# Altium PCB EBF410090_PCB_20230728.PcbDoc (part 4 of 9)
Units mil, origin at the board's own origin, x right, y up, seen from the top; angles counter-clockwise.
Board outline 5393.69 x 3858.26 mil, 6 copper layers (TOP, GND02, ART03, ART04, PWR05, BOTTOM), stack 47.2 mil thick; 570 components, 437 nets, 2015 pads, 1260 vias.
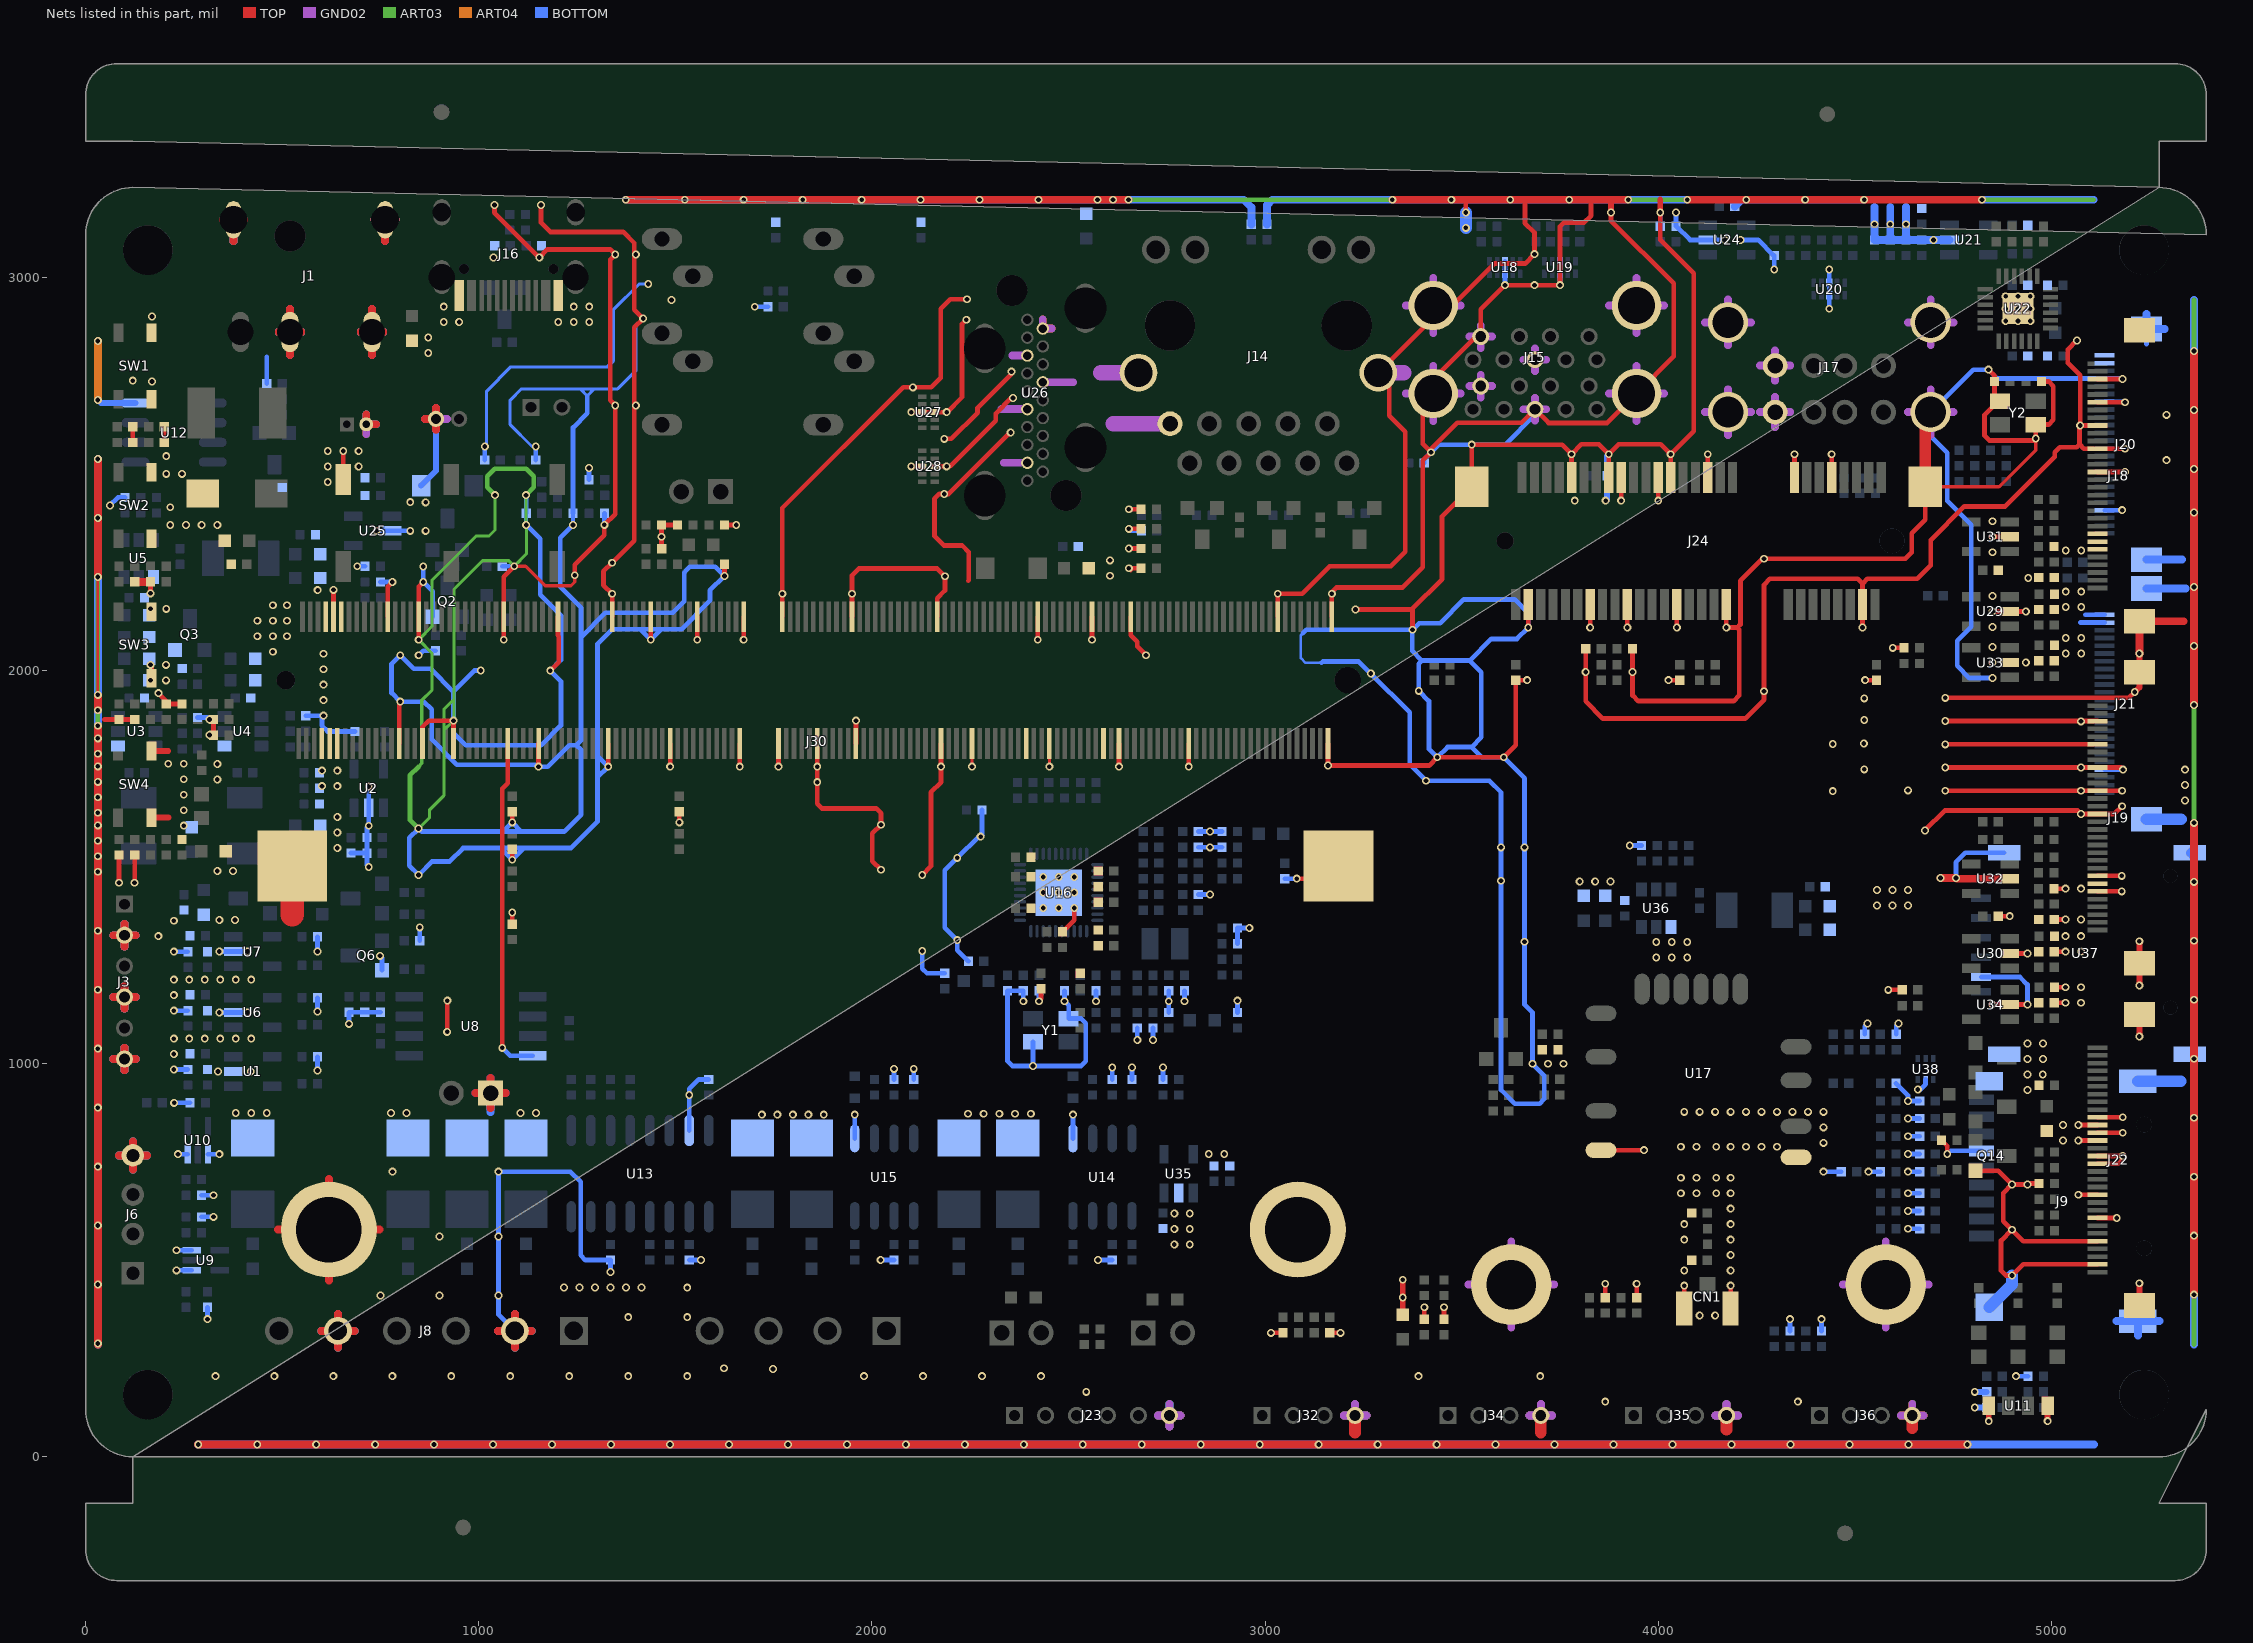
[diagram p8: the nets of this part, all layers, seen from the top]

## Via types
v1: diameter 20, hole 12, TOP to BOTTOM, 1260 vias

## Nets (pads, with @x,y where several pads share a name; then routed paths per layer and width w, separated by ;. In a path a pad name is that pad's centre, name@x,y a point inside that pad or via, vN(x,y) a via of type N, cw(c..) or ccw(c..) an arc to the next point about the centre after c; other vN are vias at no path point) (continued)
GND: C1.2 C2.2 C3.2 C4.2 C5.2 C6.2 C9.2 C10.2 C11.2 C12.2 C13.2 C14.2 C15.2 C16.2 C17.2 C18.1 C21.2 C22.2 C23.2 C24.2 C25.2 C26.2 C27.1 C30.2 C31.2 C32.2 C33.2 C34.2 C35.2 C36.2 C37.1 C39.2 C40.2 C41.2 C42.2 C43.2 C47.2 C48.2 C49.2 C50.2 C51.2 C52.2 C53.2 C54.2 C55.2 C56.2 C57.2 C58.2 C59.2 C60.2 C61.2 C62.2 C63.2 C64.2 C65.2 C66.2 C67.2 C68.2 C69.2 C70.2 C73.2 C74.2 C75.2 C76.2 C79.2 C80.2 C81.2 C82.2 C83.2 C84.2 C85.2 C86.2 C87.2 C88.2 C89.2 C90.2 C91.2 C92.2 C93.2 C94.2 C95.2 C96.2 C97.2 C98.2 C99.2 C100.2 C101.2 C102.2 C103.2 C104.2 C105.2 C107.2 C108.2 C110.2 C111.2 C112.2 C113.2 C116.2 C117.2 C118.2 C119.2 C120.1 C121.2 C122.2 C123.2 C124.2 C125.2 C126.2 C127.2 C128.2 C129.2 C130.2 C131.2 C136.2 C137.2 C138.2 C139.2 C140.2 C141.2 C142.2 C143.2 C144.2 C145.2 C150.2 C151.2 C152.2 C153.2 C154.2 C155.2 C162.2 C163.2 C164.2 C166.2 C167.2 C170.2 C171.2 C172.2 C173.2 C174.2 C175.2 C176.2 C177.2 C178.2 C181.2 C182.2 C183.2 C184.2 C185.2 C186.2 C187.2 C191.2 C192.2 C431.2 CN1.2 CN1.3 D1.1 D2.2 D7.1 D8.1 D9.1 D10.1 D11.1 D12.1 D13.1 D14.1 D15.1 D16.1 D17.1 D18.1 D21.1 D22.1 D23.1 D24.1 D28.1 D29.1 D30.1 D31.1 D32.1 D33.1 D34.1 D35.1 D36.1 D47.1 D48.1 D49.1 D50.1 D51.1 D52.1 D53.1 D54.1 J1.1 J1.2 J1.3 J1.5 J2.2 J3.2 J3.4 J3.6 J5.1 J6.4 J7.2 J8.2 J8.5 J9.6 J9.10 J9.11 J9.12 J9.13 J14.10 J14.15 J14.16 J15.4 J15.7 J15.13 J15.16 J15.19 J15.20 J15.21 J15.22 J16.A1 J16.A12 J16.B1 J16.B12 J17.4 J17.5 J17.6 J17.10 J17.11 J17.12 J18.6 J18.7 J18.8 J18.16 J18.19 J18.22 J18.25 J18.28 J18.31 J18.32 J19.6 J19.7 J19.8 J19.16 J19.19 J19.22 J19.25 J19.28 J19.31 J19.32 J20.4 J20.18 J20.21 J20.23 J20.24 J20.25 J20.26 J21.4 J21.23 J21.24 J21.25 J21.26 J22.2 J22.5 J22.8 J22.11 J22.15 J22.16 J22.18 J22.19 J22.20 J22.21 J22.31 J22.32 J23.6 J24.4 J24.9 J24.15 J24.18 J24.21 J24.26 J24.27 J24.29 J24.34 J24.35 J24.37 J24.40 J24.43 J24.50 J24.53 J24.54 J30.1 J30.2 J30.15 J30.38 J30.53 J30.56 J30.60 J30.63 J30.74 J30.77 J30.80 J30.94 J30.102 J30.103 J30.124 J30.125 J30.134 J30.143 J30.144 J30.145 J30.146 J30.157 J30.164 J30.169 J30.179 J30.180 J30.193 J30.198 J30.206 J30.207 J30.220 J30.228 J30.229 J30.234 J30.237 J30.249 J30.250 J30.251 J30.252 J30.253 J30.254 J30.261 J30.262 J32.4 J34.4 J35.4 J36.4 L8.2 L9.2 Q2.2 Q3.2 Q6.2 Q14.2 R2.2 R5.2 R6.2 R8.2 R13.2 R15.2 R18.2 R21.2 R22.2 R25.2 R30.2 R32.2 R34.2 R36.2 R75.2 R76.2 R77.2 R78.2 R98.2 R103.2 R104.2 R105.2 R111.2 R114.2 R115.2 R116.2 R121.1 R144.2 R148.2 R151.2 R153.2 R155.2 R173.2 R174.2 R175.2 R176.2 R182.2 R188.2 R192.1 R195.2 R199.2 R205.2 R219.2 R220.2 R221.2 SS1.1 SS2.1 SS5.1 SS6.1 SW1.1 SW1.2 SW2.1 SW2.2 SW3.1 SW3.2 SW4.1 SW4.2 U1.2 U2.2 U3.1 U4.1 U5.1 U6.2 U7.2 U8.4 U9.1 U9.3 U10.1 U10.3 U11.1 U11.4 U12.4 U13.15 U14.5 U15.5 U16.41 U17.1 U17.5 U18.3 U18.8 U19.3 U19.8 U20.3 U20.8 U21.2 U22.25 U24.2 U25.2 U26.2 U26.5 U26.8 U26.11 U26.17 U27.3 U27.8 U28.3 U28.8 U29.2 U30.2 U31.2 U32.2 U33.2 U34.2 U35.2 U36.1 U37.5 U37.8 U37.9 U37.10 U37.11 U38.2 Y1.2 Y1.4 Y2.2 Y2.4 Z1.1 Z2.2 Z3.2 Z4.1 Z5.1 Z7.1 Z8.1 Z9.1 Z10.1 Z11.1 Z13.1 Z23.1 | length 106230.6
  TOP w6.8: v1(31,1937.88) v1(31,2237.88)
  TOP w8: v1(1090,2265) 1119,2265 1168.59,2215.41 1234.41,2215.41 1244,2225 v1(1244,2242) ; v1(2254.41,1755.23) J30.94@2254.41,1813.7 ; v1(2451.26,1755.23) J30.74@2451.26,1813.7 ; J24.54@4679.19,2467.26 4679.45,2467 4867,2467 4960,2560 v1(4960,2590)
  TOP w12: 47.18,1875.32 Z5.1@85,1875.32 C63.2@125,1875.32 ; v1(85,1460) Z23.1@85,1530.32 ; C60.2@119.68,2580 Z1.1@119.68,2620 ; v1(124.37,1460) 125,1460.63 C192.2@125,1530.32 ; v1(165,2014.14) 167.63,2011.51 SW3.2@167.63,1980.06 ; v1(165,2196) C37.1@165,2225.32 ; v1(185,1942.15) 205,1922.15 C18.1@205,1914.68 R8.2@245,1914.68 ; Z4.1@199.68,2580 C61.2@199.68,2620 ; C27.1@325.32,1835 R15.2@325.32,1875 ; J30.251@630.39,2136.54 v1(630.39,2205) ; C1.2@655,2485.24 v1(655,2558) ; J30.237@768.19,2136.54 768.19,2213.19 v1(780,2225) ; J30.234@797.71,1813.7 797.71,1918.3 v1(800,1920.59) ; v1(846.93,2078.07) J30.229@846.93,2136.54 846.93,2213.19 v1(858.74,2225) ; J30.228@856.76,1813.7 856.76,1856.27 872.66,1872.17 v1(935.5,1872.17) J30.220@935.5,1813.7 ; v1(919.4,1080.63) 920,1081.23 v1(920,1160) ; v1(1039.63,3184) 1039.63,3164.38 v1(1153.94,3050.07) 1174.63,3070.76 1334.12,3070.76 v1(1346.88,3058) 1334,3045.12 1334,2686.88 v1(1346.88,2674) 1346.88,2397.83 v1(1319.37,2370.32) 1319.37,2344.38 1244,2269.01 v1(1244,2242) ; v1(1059.51,1040) 1059.51,1699.51 1073.3,1713.3 J30.206@1073.3,1813.7 ; v1(1063.46,2078.07) J30.207@1063.46,2136.54 1063.46,2238.46 v1(1090,2265) ; C53.2@1085,1354.68 v1(1085,1384.15) ; v1(1085,1518.52) R36.2@1085,1545.32 ; v1(1085,1613.52) C56.2@1085,1640.32 ; v1(1152.04,1755.23) J30.198@1152.04,1813.7 ; v1(1158.37,3184) 1158.37,3138.63 1181.77,3115.23 1367.29,3115.23 1395.35,3087.17 1395.35,3062 v1(1399.35,3058) 1395.35,3054 1395.35,2917.65 v1(1418,2895) 1395.35,2872.35 1395.35,2678 v1(1399.35,2674) 1395.35,2670 1395.35,2330.05 v1(1339.05,2273.75) 1317.05,2251.75 1317.05,2217.01 v1(1339.05,2195.01) J30.179@1339.05,2136.54 ; v1(1181.57,1999.33) 1203.57,2021.33 1203.57,2087.19 1201.26,2089.5 J30.193@1201.26,2136.54 ; v1(1329.2,1755.23) J30.180@1329.2,1813.7 ; v1(1437.48,2078.07) J30.169@1437.48,2136.54 ; C185.2@1465,2309.68 1464.68,2310 v1(1464.68,2340) C186.2@1464.68,2370 Z7.1@1505.32,2370 ; v1(1486.68,1755.23) J30.164@1486.68,1813.7 ; v1(1510,1613.52) R151.2@1510,1640.32 ; v1(1555.58,2078.07) J30.157@1555.59,2136.54 ; v1(1624.68,2240) R220.2@1624.68,2270 ; Z10.1@1624.68,2370 v1(1654.68,2370) ; v1(1663.85,1755.23) J30.146@1663.85,1813.7 ; v1(1673.69,2078.07) J30.145@1673.7,2136.54 ; v1(1762.28,1755.23) J30.144@1762.28,1813.7 ; J30.143@1772.12,2136.54 v1(1772.12,2195.01) 1772.12,2413.12 2079.51,2720.51 2103.49,2720.51 v1(2104,2720) 2151,2720 2175,2744 2175,2920 2199,2944 v1(2242,2944) ; J30.134@1860.71,1813.7 v1(1860.71,1755.23) v1(1860.71,1715.86) 1860.71,1661 1872.71,1649 2011,1649 2023,1637 v1(2023,1607.6) 2001,1585.6 2001,1514.84 v1(2023,1492.84) ; J30.125@1949.29,2136.54 v1(1949.29,2195.01) 1949.29,2242 1966.29,2259 2165.89,2259 v1(2185.51,2239.38) 2185.51,2203.26 2165.82,2183.57 J30.103@2165.82,2136.54 ; J30.124@1959.13,1813.7 v1(1959.13,1872.17) ; v1(2100,2519) U28.8@2128.25,2519 ; v1(2100,2657) U27.8@2128.25,2657 U27.3@2159.75,2657 v1(2190,2657) 2191.07,2657 2229,2694.93 2229,2881 v1(2240,2892) ; v1(2128,1479.6) 2150,1501.6 2150,1690 2175.67,1715.67 v1(2175.67,1755.23) J30.102@2175.67,1813.7 ; U28.3@2159.75,2519 v1(2190,2519) 2199,2519 2315,2635 2315,2653.42 2354.58,2693 v1(2359,2693) ; v1(2184,2589) 2201.99,2589 2268.68,2655.69 2268.68,2668.33 2355,2754.65 v1(2355,2760) ; 2245,2228 2246,2229 2246,2301 2229,2318 2183,2318 2159,2342 2159,2437 2171,2449 v1(2184,2449) 2195,2449 2351.35,2605.35 v1(2352.65,2605.35) ; v1(2421.72,2078.07) J30.77@2421.73,2136.54 ; v1(2425,1158.52) 2425,1160 2430,1165 C100.2@2430,1190.32 ; R115.2@2484.68,1335 2514.37,1364.69 v1(2514.37,1395.63) ; v1(2559.51,2078.07) J30.63@2559.52,2136.54 ; v1(2628.42,1755.23) J30.56@2628.42,1813.7 ; v1(2653.36,2310) D30.1@2684.5,2310 ; v1(2653.36,2360) D28.1@2684.5,2360 ; v1(2653.36,2410) D29.1@2684.5,2410 ; J30.53@2657.95,2136.54 2657.95,2089.49 2675,2072.44 2675,2061 v1(2697.3,2038.7) ; v1@2657.95,2255.41 v1(2653.36,2260) D31.1@2684.5,2260 ; v1(2805.59,1755.23) J30.38@2805.59,1813.7 ; v1(3015,315) D50.1@3045.32,315 ; J30.15@3031.96,2136.54 v1(3031.98,2195.01) ; v1(3031.98,2195.01) 3094,2195.01 3163.99,2265 3320,2265 3356.65,2301.65 3356.65,2607.35 3315.65,2648.35 3315.65,2729.64 J14.15@3287.85,2757.44 3427.62,2897.21 J15.19@3427.62,2927.91 3475.91,2927.91 3583,3035 3661.26,3035 v1(3685,3058.74) 3685,3114 3661,3138 3661,3196.34 3660,3197.34 ; v1(3080.32,1470.32) 3154.13,1470.32 J30.261@3186.49,1502.68 ; J30.2@3159.92,1813.7 v1(3159.92,1757.92) 3416.92,1757.92 v1(3438,1779) v1(3607,1779) 3637.85,1809.85 C184.2@3637.85,1975.32 v1(3666.57,1975.32) ; D49.1@3164.68,315 v1(3191.48,315) ; J30.1@3169.76,2136.54 v1(3169.78,2195.01) ; v1(3169.78,2195.01) 3169.78,2199 3181.78,2211 3350.01,2211 3401.12,2262.11 3401.12,2534 v1(3422.12,2555) ; v1(3230,2155) 3372.99,2155 ; v1(3375,2103.52) 3375,2152.99 3372.99,2155 ; D48.1@3405,349.68 v1(3405,380) ; D47.1@3455,349.68 v1(3455,380) ; 3509,3197.34 3510.63,3195.71 v1(3510.63,3165) ; v1(3669.35,2108.92) J24.50@3669.35,2168.04 ; J24.43@3779.59,2490.88 v1(3779.59,2550) ; D36.1@3815.32,2055 v1(3815.32,1995.88) 3815.32,1921.68 3859.35,1877.65 4221,1877.65 4269,1925.65 v1(4269,1947) 4269,2218 4284,2233 4507.74,2233 4519.74,2221 ; v1(3826.83,2108.92) J24.40@3826.83,2168.04 ; 3828,3197.34 3829,3196.34 3829,3157 3811,3139 3760,3139 3750,3129 v1(3750,2980) v1(3685,2980) v1(3610,2980) 3548.49,2918.49 J15.4@3548.49,2849.17 3536.17,2849.17 3427.62,2740.62 J15.20@3427.62,2704.29 3401.12,2677.79 3401.12,2576 v1(3422.12,2555) ; U17.5@3854.39,779.83 v1(3964,779.83) ; D52.1@3865,404.68 v1(3865,440) ; J24.37@3874.07,2490.88 v1(3874.07,2550) ; v1(3879.53,3164.61) 3879.53,3143.95 4039.24,2984.24 4039.24,2798.58 J15.21@3944.95,2704.29 3870.01,2629.35 3721.06,2629.35 J15.16@3686.28,2664.13 3652.15,2630 3488.62,2630 3422.12,2563.5 v1(3422.12,2555) ; v1(3905.57,2431.76) J24.35@3905.57,2490.88 ; v1(3921.32,2108.92) J24.34@3921.32,2168.04 ; D35.1@3934.68,2055 v1(3934.68,1995.88) 3934.68,1936.44 3949,1922.12 4191.65,1922.12 4206,1936.47 4206,2104.01 4201.09,2108.92 ; D51.1@3945,404.68 v1(3945,440) ; v1(4000.06,2431.76) J24.29@4000.06,2490.88 ; v1(4005,3165) 4005,3095 4090,3010 4090,2608.45 v1(4031.55,2550) ; v1(4026.28,1975.32) C181.2@4055,1975.32 ; J24.27@4031.55,2490.88 v1(4031.55,2550) ; v1(4047.3,2108.92) J24.26@4047.3,2168.04 ; CN1.3@4065.94,376.8 v1(4065.94,435.11) ; J24.21@4126.04,2490.88 v1(4126.04,2550) ; J24.18@4173.29,2168.04 v1(4173.29,2108.92) 4201.09,2108.92 ; CN1.2@4184.06,376.8 v1(4184.06,435.11) ; J24.15@4346.51,2490.88 v1(4346.51,2550) ; J24.9@4441,2490.88 v1(4441,2550) ; v1(4519.74,2108.92) J24.4@4519.74,2168.04 4519.74,2221 ; v1(4526.28,1975.32) C183.2@4555,1975.32 ; v1(4585,1187.4) C153.2@4620.32,1187.4 ; v1(4596.6,2057.4) C150.2@4625.32,2057.4 ; v1(4678.26,1593) 4728.76,1643.5 5066.35,1643.5 v1(5075,1634.85) J19.16@5117.47,1634.85 5160.32,1634.85 v1(5180,1654.53) ; J24.54@4679.19,2467.26 4679.19,2383.19 4644.65,2348.65 4644.65,2300 4628.65,2284 4613.44,2284 4613.4,2283.96 4575.7,2283.96 4575.66,2284 v1(4269,2284) 4264.61,2284 4209,2228.39 4209,2116.83 4201.09,2108.92 ; R199.2@4720.32,805 4735,790.32 v1(4735,770) ; v1(4730,1693.9) v1(5075,1693.9) J19.19@5117.47,1693.9 v1(5180,1693.9) ; v1(4730,1752.96) v1(5075,1752.96) J19.22@5117.47,1752.96 5177.04,1752.96 v1(5182.32,1747.68) ; v1(4730,1812.01) J19.25@5117.47,1812.01 ; v1(4730,1871.07) 5074.37,1871.07 v1(5075,1870.44) 5075.63,1871.07 J19.28@5117.47,1871.07 ; v1(4730,1930.13) 5197.13,1930.13 v1(5212,1945) ; Q14.2@4806.5,727.5 4864.76,727.5 v1(4899.64,692.62) ; v1(4840,2765) 4855.32,2749.68 C119.2@4855.32,2735 4855.32,2698.93 Y2.4@4869.72,2684.53 4864.52,2684.53 4830,2650.01 4830,2597 4842,2585 4955,2585 v1(4960,2590) 4960.28,2590.28 Y2.2@4960.28,2625.47 4993,2625.47 5005,2637.47 5005,2723 4993,2735 C120.1@4974.68,2735 ; v1(4849.41,1150) U34.2@4894.21,1150 v1(4939.01,1150) ; v1(4850,2150) U29.2@4894.21,2150 v1(4935,2150) ; v1(4850,2340) U31.2@4894.21,2340 ; C136.2@4864.68,1375 v1(4894,1375) ; U30.2@4894.21,1280 v1(4939.01,1280) ; R192.1@4968.32,695 4941.39,695 v1(4939.01,692.62) v1(4899.64,692.62) ; R176.2@5006.68,1445 v1(5035.68,1445) ; C155.2@5007,1154.68 v1(5036,1154.68) ; C138.2@5007,1284.68 v1(5036,1284.68) ; C145.2@5007,1366.32 v1(5036,1366.32) ; R188.2@5007.68,1194 v1(5036,1194.05) v1(5036,1194.05) ; v1(5065,2839.37) 5041.71,2816.08 5041.71,2782.12 5073.04,2750.79 v1(5073.04,2622.96) ; v1(5068.63,666.42) J22.11@5117.47,666.42 ; v1(5068.63,804.22) J22.18@5117.47,804.22 ; v1(5068.63,843.59) J22.20@5117.47,843.59 ; J22.2@5117.47,489.26 4928.1,489.26 v1(4900,461.16) 4884,461.16 4872,473.16 4872,549.73 v1(4899.64,577.37) ; J22.5@5117.47,548.31 4928.7,548.31 v1(4899.64,577.37) ; J22.8@5117.47,607.37 v1(5166.31,607.37) ; J22.15@5117.47,745.16 5169.46,745.16 5181.46,757.16 v1(5181.46,764.85) J22.16@5117.47,764.85 ; J22.19@5117.47,823.9 v1(5181.46,823.9) ; J22.21@5117.47,863.27 v1(5181.46,863.27) ; J19.6@5117.47,1438 v1(5179,1438) ; J19.8@5117.47,1477.37 v1(5179,1477.37) ; J18.16@5117.47,2504.85 v1(5187,2504.85) ; J18.22@5117.47,2622.96 v1(5073.04,2622.96) ; J18.25@5117.47,2682.01 v1(5187,2682.01) ; J18.28@5117.47,2741.07 v1(5181,2741.07) ; v1(5187,2563.9) J18.19@5117.47,2563.9 5082.69,2563.9 5071.59,2575 ; 3372.99,2155 3450.12,2232.13 3450.12,2391.73 J24.53@3525.65,2467.26 v1(3525.65,2574.35) 3755.24,2574.35 v1(3779.59,2550) ; v1(3779.59,2550) 3804.59,2575 3849.07,2575 v1(3874.07,2550) ; v1(3874.07,2550) 3899.07,2575 4006.55,2575 v1(4031.55,2550) ; 4519.74,2221 4531.74,2233 4659,2233 4693,2267 4693,2331.6 4778.4,2417 4882.7,2417 5008.63,2542.93 5008.63,2554.59 5021.51,2567.47 5064.06,2567.47 5071.59,2575 ; v1(4899.64,577.37) 4877.64,599.37 4877.64,670.62 v1(4899.64,692.62) ; 5071.59,2575 5071.59,2621.51 v1(5073.04,2622.96)
  TOP w15: SW4.2@167.01,1625.64 210.64,1625.64 ; SW4.1@167.01,1794.94 210.06,1794.94 ; C431.2@3350,361.5 v1(3350,405) v1(3350,450) ; v1(3879.53,3164.61) 3880,3165.08 3880,3197.34 ; v1(4005,3165) 4005,3197.34 ; v1(4840.52,90.52) U11.1@4840.52,129.26 ; v1(4990.52,90.52) U11.4@4990.52,129.26 ; v1(5212,1945) 5223.77,1956.77 J19.31@5223.77,1995.08 v1(5223.77,2042.95) ; J22.32@5223.77,384.92 v1(5223.77,441.23) ; v1(5223.77,1068.77) J22.31@5223.77,1125.08 ; v1(5223.77,1198.61) J19.32@5223.77,1254.92 v1(5223.77,1311.23)
  TOP w20: v1@31,285 v1(31,287.88) v1(31,437.88) v1(31,587.88) v1(31,737.88) v1(31,887.88) v1(31,1037.88) v1(31,1187.88) v1(31,1337.88) v1(31,1487.88) v1(31,1527.25) v1(31,1566.62) v1(31,1605.99) v1(31,1637.88) v1(31,1677.25) v1(31,1716.62) v1(31,1755.99) v1(31,1787.88) v1(31,1827.25) v1(31,1859.14) ; v1(31,1898.51) v1(31,1937.88) ; v1(31,2237.88) v1(31,2387.88) v1(31,2537.88) ; 70.06,1011.58 J3.6@98.74,1011.58 ; 70.06,1169.06 J3.4@98.74,1169.06 ; 70.06,1326.54 J3.2@98.74,1326.54 ; 84.43,766.54 J6.4@120,766.54 ; 98.74,982.9 J3.6@98.74,1011.58 ; 98.74,1040.26 J3.6@98.74,1011.58 ; 98.74,1140.38 J3.4@98.74,1169.06 ; 98.74,1197.74 J3.4@98.74,1169.06 ; 98.74,1297.86 J3.2@98.74,1326.54 ; 98.74,1355.22 J3.2@98.74,1326.54 ; 120,730.97 J6.4@120,766.54 ; 120,802.11 J6.4@120,766.54 ; R25.2@125,2225.32 C37.1@165,2225.32 ; 127.42,1011.58 J3.6@98.74,1011.58 ; 127.42,1169.06 J3.4@98.74,1169.06 ; 127.42,1326.54 J3.2@98.74,1326.54 ; 155.57,766.54 J6.4@120,766.54 ; v1@285,31 v1(286.25,31) v1(436.25,31) v1(586.25,31) v1(736.25,31) v1(886.25,31) v1(1036.25,31) v1(1186.25,31) v1(1336.25,31) v1(1486.25,31) v1(1636.25,31) v1(1786.25,31) v1(1936.25,31) v1(2086.25,31) v1(2236.25,31) v1(2386.25,31) v1(2536.25,31) v1(2686.25,31) v1(2836.25,31) v1(2986.25,31) v1(3136.25,31) v1(3286.25,31) v1(3436.25,31) v1(3586.25,31) v1(3736.25,31) v1(3886.25,31) v1(4036.25,31) v1(4186.25,31) v1(4336.25,31) v1(4486.25,31) v1(4636.25,31) v1(4786.25,31) ; 349.28,3146.28 J1.1@376,3146.28 ; 376,3092.01 J1.1@376,3146.28 ; 402.72,3146.28 J1.1@376,3146.28 ; 489.51,577.48 SS6.1@618.58,577.48 ; 491.03,2860.78 J1.2@519.7,2860.78 ; 519.7,2802.56 J1.2@519.7,2860.78 ; 519.7,2919 J1.2@519.7,2860.78 ; 548.37,2860.78 J1.2@519.7,2860.78 ; 599.2,320.17 J8.5@641.66,320.17 ; 618.58,448.41 SS6.1@618.58,577.48 ; 618.58,706.55 SS6.1@618.58,577.48 ; 641.66,277.71 J8.5@641.66,320.17 ; 641.66,362.63 J8.5@641.66,320.17 ; 684.12,320.17 J8.5@641.66,320.17 ; 699.63,2860.78 J1.3@728.3,2860.78 ; 713.59,2650.72 J7.2@713.59,2625.98 738.33,2625.98 ; 728.3,2802.56 J1.3@728.3,2860.78 ; 728.3,2919 J1.3@728.3,2860.78 ; 735.08,3146.28 J1.5@761.8,3146.28 ; 747.65,577.48 SS6.1@618.58,577.48 ; 756.97,2860.78 J1.3@728.3,2860.78 ; 761.8,3092.01 J1.5@761.8,3146.28 ; 788.52,3146.28 J1.5@761.8,3146.28 ; 863.3,2639.93 J2.2@890.99,2639.93 ; 890.99,2612.24 J2.2@890.99,2639.93 ; 890.99,2667.62 J2.2@890.99,2639.93 ; 991.48,925 J5.1@1030,925 ; 1030,886.48 J5.1@1030,925 ; 1030,963.52 J5.1@1030,925 ; 1049.2,320.17 J8.2@1091.66,320.17 ; 1068.52,925 J5.1@1030,925 ; 1091.66,277.71 J8.2@1091.66,320.17 ; 1091.66,362.63 J8.2@1091.66,320.17 ; 1134.12,320.17 J8.2@1091.66,320.17 ; v1(1373.69,3197.34) v1(1523.69,3197.34) v1(1673.69,3197.34) v1(1823.69,3197.34) v1(1973.69,3197.34) v1(2123.69,3197.34) v1(2273.69,3197.34) v1(2423.69,3197.34) v1(2573.69,3197.34) v1(2613.06,3197.34) v1(2652.43,3197.34) ; v1(3323.69,3197.34) v1(3473.69,3197.34) 3509,3197.34 v1(3623.69,3197.34) 3660,3197.34 v1(3773.69,3197.34) 3828,3197.34 3880,3197.34 v1(3923.69,3197.34) ; v1(4073.69,3197.34) v1(4223.69,3197.34) v1(4373.69,3197.34) v1(4523.69,3197.34) v1(4823.69,3197.34) ; v1(4717.82,1471.97) v1(4757.19,1471.97) 4759.16,1470 U32.2@4894.21,1470 ; v1(5223.77,2042.95) J18.32@5223.77,2124.92 5335.92,2124.92 ; v1(5362.69,412.23) v1(5362.69,562.23) v1(5362.69,712.23) v1(5362.69,862.23) v1(5362.69,1012.23) v1(5362.69,1162.23) v1(5362.69,1312.23) v1(5362.69,1462.23) v1(5362.69,1612.23) ; v1(5362.69,1912.23) v1(5362.69,2062.23) v1(5362.69,2212.23) v1(5362.69,2401.6) v1(5362.69,2512.23) v1(5362.69,2662.23) v1(5362.69,2812.23)
  TOP w30: 3228.86,61.14 J32.4@3228.86,105.01 ; 3701.3,61.3 J34.4@3701.3,105.01 ; 4173.74,68.74 J35.4@4173.74,105.01 ; 4646.18,72.18 J36.4@4646.18,105.01 ; J24.54@4679.19,2467.26 4679.19,2643.26 J17.6@4692.97,2657.04
  TOP w60: 525.07,1378.07 J30.262@525.07,1502.68
  GND02 w20: 70.06,1011.58 J3.6@98.74,1011.58 ; 70.06,1169.06 J3.4@98.74,1169.06 ; 70.06,1326.54 J3.2@98.74,1326.54 ; 84.43,766.54 J6.4@120,766.54 ; 98.74,982.9 J3.6@98.74,1011.58 ; 98.74,1040.26 J3.6@98.74,1011.58 ; 98.74,1140.38 J3.4@98.74,1169.06 ; 98.74,1197.74 J3.4@98.74,1169.06 ; 98.74,1297.86 J3.2@98.74,1326.54 ; 98.74,1355.22 J3.2@98.74,1326.54 ; 120,730.97 J6.4@120,766.54 ; 120,802.11 J6.4@120,766.54 ; 127.42,1011.58 J3.6@98.74,1011.58 ; 127.42,1169.06 J3.4@98.74,1169.06 ; 127.42,1326.54 J3.2@98.74,1326.54 ; 155.57,766.54 J6.4@120,766.54 ; 349.28,3146.28 J1.1@376,3146.28 ; 376,3092.01 J1.1@376,3146.28 ; 402.72,3146.28 J1.1@376,3146.28 ; 491.03,2860.78 J1.2@519.7,2860.78 ; 509.2,577.48 SS6.1@618.58,577.48 ; 519.7,2802.56 J1.2@519.7,2860.78 ; 519.7,2919 J1.2@519.7,2860.78 ; 548.37,2860.78 J1.2@519.7,2860.78 ; 599.2,320.17 J8.5@641.66,320.17 ; 618.58,468.1 SS6.1@618.58,577.48 ; 618.58,686.86 SS6.1@618.58,577.48 ; 641.66,277.71 J8.5@641.66,320.17 ; 641.66,362.63 J8.5@641.66,320.17 ; 684.12,320.17 J8.5@641.66,320.17 ; 699.63,2860.78 J1.3@728.3,2860.78 ; 713.59,2601.24 J7.2@713.59,2625.98 ; 713.59,2650.72 J7.2@713.59,2625.98 ; 727.96,577.48 SS6.1@618.58,577.48 ; 728.3,2802.56 J1.3@728.3,2860.78 ; 728.3,2919 J1.3@728.3,2860.78 ; 735.08,3146.28 J1.5@761.8,3146.28 ; 738.33,2625.98 J7.2@713.59,2625.98 ; 756.97,2860.78 J1.3@728.3,2860.78 ; 761.8,3092.01 J1.5@761.8,3146.28 ; 788.52,3146.28 J1.5@761.8,3146.28 ; 863.3,2639.93 J2.2@890.99,2639.93 ; 890.99,2612.24 J2.2@890.99,2639.93 ; 890.99,2667.62 J2.2@890.99,2639.93 ; 918.68,2639.93 J2.2@890.99,2639.93 ; 991.48,925 J5.1@1030,925 ; 1030,886.48 J5.1@1030,925 ; 1030,963.52 J5.1@1030,925 ; 1049.2,320.17 J8.2@1091.66,320.17 ; 1068.52,925 J5.1@1030,925 ; 1091.66,277.71 J8.2@1091.66,320.17 ; 1091.66,362.63 J8.2@1091.66,320.17 ; 1134.12,320.17 J8.2@1091.66,320.17 ; 2329.51,2664.49 U26.11@2395.17,2664.49 ; 2335.92,2528.08 U26.17@2395.17,2528.08 ; 2356.91,2800.91 U26.5@2395.17,2800.91 ; U26.8@2434.54,2732.92 2512.08,2732.92 ; 2434.54,2892.23 U26.2@2434.54,2869.46 2457.31,2869.46 ; 2727.74,105.01 J23.6@2756.42,105.01 ; 2756.42,76.33 J23.6@2756.42,105.01 ; 2756.42,133.69 J23.6@2756.42,105.01 ; 2785.1,105.01 J23.6@2756.42,105.01 ; 2973.76,577.48 SS5.1@3083.14,577.48 ; 3083.14,468.1 SS5.1@3083.14,577.48 ; 3083.14,686.86 SS5.1@3083.14,577.48 ; 3192.52,577.48 SS5.1@3083.14,577.48 ; 3200.18,105.01 J32.4@3228.86,105.01 ; 3228.86,76.33 J32.4@3228.86,105.01 ; 3228.86,133.69 J32.4@3228.86,105.01 ; 3257.54,105.01 J32.4@3228.86,105.01 ; 3357.61,2704.29 J15.20@3427.62,2704.29 ; 3357.61,2927.91 J15.19@3427.62,2927.91 ; 3427.62,2634.28 J15.20@3427.62,2704.29 ; 3427.62,2774.3 J15.20@3427.62,2704.29 ; 3427.62,2857.9 J15.19@3427.62,2927.91 ; 3427.62,2997.92 J15.19@3427.62,2927.91 ; 3497.63,2704.29 J15.20@3427.62,2704.29 ; 3497.63,2927.91 J15.19@3427.62,2927.91 ; 3516.65,437.78 SS2.1@3626.03,437.78 ; 3519.81,2723.19 J15.13@3548.49,2723.19 ; 3519.81,2849.17 J15.4@3548.49,2849.17 ; 3548.49,2694.51 J15.13@3548.49,2723.19 ; 3548.49,2751.87 J15.13@3548.49,2723.19 ; 3548.49,2820.49 J15.4@3548.49,2849.17 ; 3548.49,2877.85 J15.4@3548.49,2849.17 ; 3577.17,2723.19 J15.13@3548.49,2723.19 ; 3577.17,2849.17 J15.4@3548.49,2849.17 ; 3626.03,328.4 SS2.1@3626.03,437.78 ; 3626.03,547.16 SS2.1@3626.03,437.78 ; 3657.6,2664.13 J15.16@3686.28,2664.13 ; 3657.6,2790.12 J15.7@3686.28,2790.12 ; 3672.62,105.01 J34.4@3701.3,105.01 ; 3686.28,2635.45 J15.16@3686.28,2664.13 ; 3686.28,2692.81 J15.16@3686.28,2664.13 ; 3686.28,2761.44 J15.7@3686.28,2790.12 ; 3686.28,2818.8 J15.7@3686.28,2790.12 ; 3701.3,76.33 J34.4@3701.3,105.01 ; 3701.3,133.69 J34.4@3701.3,105.01 ; 3714.96,2664.13 J15.16@3686.28,2664.13 ; 3714.96,2790.12 J15.7@3686.28,2790.12 ; 3729.98,105.01 J34.4@3701.3,105.01 ; 3735.41,437.78 SS2.1@3626.03,437.78 ; 3874.94,2704.29 J15.21@3944.95,2704.29 ; 3874.94,2927.91 J15.22@3944.95,2927.91 ; 3944.95,2634.28 J15.21@3944.95,2704.29 ; 3944.95,2774.3 J15.21@3944.95,2704.29 ; 3944.95,2857.9 J15.22@3944.95,2927.91 ; 3944.95,2997.92 J15.22@3944.95,2927.91 ; 4014.96,2704.29 J15.21@3944.95,2704.29 ; 4014.96,2927.91 J15.22@3944.95,2927.91 ; 4119.03,2657.04 J17.5@4177.23,2657.04 ; 4119.03,2885.39 J17.11@4177.23,2885.39 ; 4145.06,105.01 J35.4@4173.74,105.01 ; 4173.74,76.33 J35.4@4173.74,105.01 ; 4173.74,133.69 J35.4@4173.74,105.01 ; 4177.23,2598.84 J17.5@4177.23,2657.04 ; 4177.23,2715.24 J17.5@4177.23,2657.04 ; 4177.23,2827.19 J17.11@4177.23,2885.39 ; 4177.23,2943.59 J17.11@4177.23,2885.39 ; 4202.42,105.01 J35.4@4173.74,105.01 ; 4235.43,2657.04 J17.5@4177.23,2657.04 ; 4235.43,2885.39 J17.11@4177.23,2885.39 ; 4258.78,2657.04 J17.4@4297.3,2657.04 ; 4258.78,2775.15 J17.10@4297.3,2775.15 ; 4297.3,2618.52 J17.4@4297.3,2657.04 ; 4297.3,2695.56 J17.4@4297.3,2657.04 ; 4297.3,2736.63 J17.10@4297.3,2775.15 ; 4297.3,2813.67 J17.10@4297.3,2775.15 ; 4335.82,2657.04 J17.4@4297.3,2657.04 ; 4335.82,2775.15 J17.10@4297.3,2775.15 ; 4469.41,437.78 SS1.1@4578.79,437.78 ; 4578.79,328.4 SS1.1@4578.79,437.78 ; 4578.79,547.16 SS1.1@4578.79,437.78 ; 4617.5,105.01 J36.4@4646.18,105.01 ; 4634.77,2657.04 J17.6@4692.97,2657.04 ; 4634.77,2885.39 J17.12@4692.97,2885.39 ; 4646.18,76.33 J36.4@4646.18,105.01 ; 4646.18,133.69 J36.4@4646.18,105.01 ; 4674.86,105.01 J36.4@4646.18,105.01 ; 4688.17,437.78 SS1.1@4578.79,437.78 ; 4692.97,2598.84 J17.6@4692.97,2657.04 ; 4692.97,2715.24 J17.6@4692.97,2657.04 ; 4692.97,2827.19 J17.12@4692.97,2885.39 ; 4692.97,2943.59 J17.12@4692.97,2885.39 ; 4751.17,2657.04 J17.6@4692.97,2657.04 ; 4751.17,2885.39 J17.12@4692.97,2885.39
  GND02 w40: 2582.56,2757.44 J14.16@2678.01,2757.44 ; 2614.52,2627.52 J14.10@2758.13,2627.52 ; J14.15@3287.85,2757.44 3352.44,2757.44
  ART03 w8: v1(846.76,1597.75) 875,1625.99 875,1645.56 911,1681.56 911,1847.67 ; 846.76,1755.23 855,1763.47 855,1923.8 881,1949.8 881,2044 v1(846.93,2078.07) 881,2112.14 881,2229.8 993.2,2342 1026,2342 1041.26,2357.26 v1(1041.26,2445.87) ; v1(1120,2445.87) 1120,2370.32 v1(1120.32,2370) 1121.37,2368.95 1121.37,2296.37 v1(1090,2265) 1076,2279 1009.4,2279 937,2206.6 937,1926.6 ; 911,1847.67 v1(935.5,1872.17) 937,1873.67 937,1926.6 ; 911,1847.67 911,1900.6 937,1926.6
  ART03 w12: v1@31,285 v1(31,287.88) v1(31,437.88) v1(31,587.88) ; v1(31,737.88) v1(31,887.88) v1(31,1037.88) v1(31,1187.88) v1(31,1337.88) v1(31,1487.88) v1(31,1527.25) v1(31,1566.62) v1(31,1605.99) v1(31,1637.88) v1(31,1677.25) v1(31,1716.62) v1(31,1755.99) v1(31,1787.88) v1(31,1827.25) v1(31,1859.14) v1(31,1898.51) v1(31,1937.88) v1(31,2237.88) v1(31,2387.88) v1(31,2537.88) ; v1@285,31 v1(286.25,31) v1(436.25,31) v1(586.25,31) v1(736.25,31) v1(886.25,31) v1(1036.25,31) v1(1186.25,31) v1(1336.25,31) v1(1486.25,31) v1(1636.25,31) v1(1786.25,31) v1(1936.25,31) v1(2086.25,31) v1(2236.25,31) v1(2386.25,31) v1(2536.25,31) v1(2686.25,31) v1(2836.25,31) v1(2986.25,31) v1(3136.25,31) v1(3286.25,31) v1(3436.25,31) v1(3586.25,31) v1(3736.25,31) v1(3886.25,31) v1(4036.25,31) v1(4186.25,31) v1(4336.25,31) v1(4486.25,31) v1(4636.25,31) v1(4786.25,31) ; v1(846.76,1597.75) 824.76,1619.75 824.76,1733.23 846.76,1755.23 ; v1(1041.26,2445.87) 1021.26,2465.87 1021.26,2493.53 1040.73,2513 1120.53,2513 1140,2493.53 1140,2465.87 v1(1120,2445.87) ; v1(1523.69,3197.34) v1(1673.69,3197.34) ; v1(2123.69,3197.34) v1(2273.69,3197.34) v1(2423.69,3197.34) v1(2573.69,3197.34) v1(2613.06,3197.34) v1(2652.43,3197.34) v1(3323.69,3197.34) v1(3473.69,3197.34) v1(3623.69,3197.34) v1(3773.69,3197.34) v1(3923.69,3197.34) v1(4073.69,3197.34) v1(4223.69,3197.34) v1(4373.69,3197.34) v1(4523.69,3197.34) v1(4823.69,3197.34) 5107.51,3197.34 ; 5362.69,284.99 v1(5362.69,412.23) v1(5362.69,562.23) v1(5362.69,712.23) v1(5362.69,862.23) v1(5362.69,1012.23) v1(5362.69,1162.23) v1(5362.69,1312.23) v1(5362.69,1462.23) v1(5362.69,1612.23) v1(5362.69,1912.23) v1(5362.69,2062.23) v1(5362.69,2212.23) v1(5362.69,2401.6) v1(5362.69,2512.23) v1(5362.69,2662.23) v1(5362.69,2812.23) 5362.69,2942.16
  ART03 w20: v1(31,587.88) v1(31,737.88) ; 349.28,3146.28 J1.1@376,3146.28 ; 376,3092.01 J1.1@376,3146.28 ; 402.72,3146.28 J1.1@376,3146.28 ; 491.03,2860.78 J1.2@519.7,2860.78 ; 509.2,577.48 SS6.1@618.58,577.48 ; 519.7,2919 J1.2@519.7,2860.78 ; 548.37,2860.78 J1.2@519.7,2860.78 ; 599.2,320.17 J8.5@641.66,320.17 ; 618.58,468.1 SS6.1@618.58,577.48 ; 618.58,686.86 SS6.1@618.58,577.48 ; 641.66,277.71 J8.5@641.66,320.17 ; 641.66,362.63 J8.5@641.66,320.17 ; 684.12,320.17 J8.5@641.66,320.17 ; 699.63,2860.78 J1.3@728.3,2860.78 ; 727.96,577.48 SS6.1@618.58,577.48 ; 728.3,2919 J1.3@728.3,2860.78 ; 735.08,3146.28 J1.5@761.8,3146.28 ; 756.97,2860.78 J1.3@728.3,2860.78 ; 761.8,3092.01 J1.5@761.8,3146.28 ; 788.52,3146.28 J1.5@761.8,3146.28 ; 1049.2,320.17 J8.2@1091.66,320.17 ; 1091.66,277.71 J8.2@1091.66,320.17 ; 1091.66,362.63 J8.2@1091.66,320.17 ; 1134.12,320.17 J8.2@1091.66,320.17 ; 2727.74,105.01 J23.6@2756.42,105.01 ; 2756.42,76.33 J23.6@2756.42,105.01 ; 2756.42,133.69 J23.6@2756.42,105.01 ; 2785.1,105.01 J23.6@2756.42,105.01 ; 3200.18,105.01 J32.4@3228.86,105.01 ; 3228.86,76.33 J32.4@3228.86,105.01 ; 3228.86,133.69 J32.4@3228.86,105.01 ; 3257.54,105.01 J32.4@3228.86,105.01 ; 3672.62,105.01 J34.4@3701.3,105.01 ; 3701.3,76.33 J34.4@3701.3,105.01 ; 3701.3,133.69 J34.4@3701.3,105.01 ; 3729.98,105.01 J34.4@3701.3,105.01 ; 4145.06,105.01 J35.4@4173.74,105.01 ; 4173.74,76.33 J35.4@4173.74,105.01 ; 4173.74,133.69 J35.4@4173.74,105.01 ; 4202.42,105.01 J35.4@4173.74,105.01 ; 4617.5,105.01 J36.4@4646.18,105.01 ; 4646.18,76.33 J36.4@4646.18,105.01 ; 4646.18,133.69 J36.4@4646.18,105.01 ; 4674.86,105.01 J36.4@4646.18,105.01
  ART04 w20: v1(31,2687.88) v1(31,2837.88) ; 70.06,1011.58 J3.6@98.74,1011.58 ; 70.06,1169.06 J3.4@98.74,1169.06 ; 70.06,1326.54 J3.2@98.74,1326.54 ; 84.43,766.54 J6.4@120,766.54 ; 98.74,982.9 J3.6@98.74,1011.58 ; 98.74,1040.26 J3.6@98.74,1011.58 ; 98.74,1140.38 J3.4@98.74,1169.06 ; 98.74,1197.74 J3.4@98.74,1169.06 ; 98.74,1297.86 J3.2@98.74,1326.54 ; 98.74,1355.22 J3.2@98.74,1326.54 ; 120,730.97 J6.4@120,766.54 ; 120,802.11 J6.4@120,766.54 ; 127.42,1011.58 J3.6@98.74,1011.58 ; 127.42,1169.06 J3.4@98.74,1169.06 ; 127.42,1326.54 J3.2@98.74,1326.54 ; 155.57,766.54 J6.4@120,766.54 ; 349.28,3146.28 J1.1@376,3146.28 ; 376,3092.01 J1.1@376,3146.28 ; 402.72,3146.28 J1.1@376,3146.28 ; 491.03,2860.78 J1.2@519.7,2860.78 ; 509.2,577.48 SS6.1@618.58,577.48 618.58,468.1 ; 519.7,2802.56 J1.2@519.7,2860.78 ; 519.7,2919 J1.2@519.7,2860.78 ; 548.37,2860.78 J1.2@519.7,2860.78 ; 599.2,320.17 J8.5@641.66,320.17 ; 641.66,277.71 J8.5@641.66,320.17 ; 641.66,362.63 J8.5@641.66,320.17 ; 684.12,320.17 J8.5@641.66,320.17 ; 699.63,2860.78 J1.3@728.3,2860.78 ; 713.59,2601.24 J7.2@713.59,2625.98 ; 713.59,2650.72 J7.2@713.59,2625.98 ; 728.3,2802.56 J1.3@728.3,2860.78 ; 728.3,2919 J1.3@728.3,2860.78 ; 735.08,3146.28 J1.5@761.8,3146.28 ; 738.33,2625.98 J7.2@713.59,2625.98 ; 756.97,2860.78 J1.3@728.3,2860.78 ; 761.8,3092.01 J1.5@761.8,3146.28 ; 788.52,3146.28 J1.5@761.8,3146.28 ; 863.3,2639.93 J2.2@890.99,2639.93 ; 890.99,2612.24 J2.2@890.99,2639.93 ; 890.99,2667.62 J2.2@890.99,2639.93 ; 918.68,2639.93 J2.2@890.99,2639.93 ; 1049.2,320.17 J8.2@1091.66,320.17 ; 1091.66,277.71 J8.2@1091.66,320.17 ; 1091.66,362.63 J8.2@1091.66,320.17 ; 1134.12,320.17 J8.2@1091.66,320.17 ; 2434.54,2892.23 U26.2@2434.54,2869.46 2457.31,2869.46 ; 2727.74,105.01 J23.6@2756.42,105.01 ; 2756.42,76.33 J23.6@2756.42,105.01 ; 2785.1,105.01 J23.6@2756.42,105.01 ; 3200.18,105.01 J32.4@3228.86,105.01 ; 3228.86,76.33 J32.4@3228.86,105.01 ; 3228.86,133.69 J32.4@3228.86,105.01 ; 3257.54,105.01 J32.4@3228.86,105.01 ; 3672.62,105.01 J34.4@3701.3,105.01 ; 3701.3,76.33 J34.4@3701.3,105.01 ; 3701.3,133.69 J34.4@3701.3,105.01 ; 3729.98,105.01 J34.4@3701.3,105.01 ; 4145.06,105.01 J35.4@4173.74,105.01 ; 4173.74,76.33 J35.4@4173.74,105.01 ; 4173.74,133.69 J35.4@4173.74,105.01 ; 4202.42,105.01 J35.4@4173.74,105.01 ; 4617.5,105.01 J36.4@4646.18,105.01 ; 4646.18,76.33 J36.4@4646.18,105.01 ; 4646.18,133.69 J36.4@4646.18,105.01 ; 4674.86,105.01 J36.4@4646.18,105.01
  BOTTOM w6.8: 3095.75,2094.25 3090.72,2089.22 3090.72,2031.23 3102.65,2019.3 3143.3,2019.3
  BOTTOM w8: v1(1015.32,2569.68) 1019.72,2574.08 1019.72,2710.52 1081.21,2772.01 1122.79,2772.01 1327,2772 1343,2788 1343,2918.23 1407.77,2983 v1(1431,2983) ; v1(1144.68,2569.68) 1135.32,2569.68 1079.72,2625.28 1079.72,2687.28 1108.44,2716 1258,2716 ; v1(1418,2895) 1399,2876 1399,2761.8 1353.19,2715.99 1330,2715.99 1294,2716 ; 1258,2716 1276,2698 1294,2716 ; 1258,2716 1294,2716
  BOTTOM w10: v1(1120.32,2370) Z11.1@1120.32,2400 ; v1(1239.68,2370) Z13.1@1239.68,2400
  BOTTOM w12: v1(61.68,2419.68) 81.68,2439.68 R22.2@100,2439.68 ; v1(224.21,984.68) C6.2@260,984.68 ; v1(224.21,1134.68) C43.2@260,1134.68 ; v1(224.21,1284.68) C49.2@260,1284.68 ; v1(225,900) C62.2@265.32,900 ; v1(230.91,474.09) U9.1@269.57,474.09 ; v1(230.91,525.27) U9.3@269.57,525.27 ; v1(235,769.57) U10.3@259.72,769.57 ; R6.2@284.68,1880 310,1880 v1(315,1875) ; Z2.2@294.68,610 v1(325,610) ; Z3.2@294.68,665 v1(325,665) ; v1(310,350) C59.2@310,380.32 ; U10.1@310.9,769.57 v1(340,769.57) ; v1(340,1130) U6.2@375.79,1130 v1(411.58,1130) ; v1(340,1285) U7.2@375.79,1285 v1(411.58,1285) ; D7.1@460.32,2730 460.32,2797.68 ; R13.2@559.68,1885 v1(605,1885) 600.86,1880.86 600.86,1859.14 615.32,1844.68 C9.2@685,1844.68 ; v1(589.68,982.4) C4.2@589.68,1017.4 ; v1(589.68,1132.4) C41.2@589.68,1167.4 ; v1(589.68,1285) C47.2@589.68,1322.4 ; v1(670,1101) C52.2@670,1130.32 C57.2@710,1130.32 C58.2@750,1130.32 ; R5.2@675,1535.32 715,1535.32 C11.2@715.32,1535 ; v1(690.7,2265) R153.2@710.32,2265 ; v1(720,1500) 715.32,1504.68 C11.2@715.32,1535 ; v1(720,1705) U2.2@720,1650.79 v1(720,1605) 715.32,1600.32 C10.2@715.32,1575 C11.2@715.32,1535 ; v1(740,2355) U25.2@779.21,2355 v1(825.42,2355) ; v1(748.5,1274) 753.5,1269 Q6.2@753.5,1237.5 ; C124.2@749.68,2225 v1(780,2225) ; v1(846.93,2038.7) 858.55,2050.32 R18.2@890,2050.32 ; R30.2@849.68,1312.5 v1(849.68,1346.5) ; v1(858.74,2264.37) v1(858.74,2225) 882.5,2201.24 Q2.2@882.5,2136.5 ; v1(1005,2000) 989.28,2000 935.5,1946.22 ; Z8.1@1015.32,2535 v1(1015.32,2569.68) ; v1(1059.51,1040) 1079.51,1020 U8.4@1137.48,1020 ; C30.2@1059.68,2265 v1(1090,2265) ; J8.2@1091.66,320.17 1050,361.83 v1(1050,410) v1(1050,560) v1(1050,725) 1233,725 1259.2,698.8 1259.2,512.33 1271.21,500.32 C70.2@1335,500.32 v1(1335,470) ; v1(1120,2445.87) 1120.32,2445.55 Z11.1@1120.32,2400 ; v1(1120.32,2370) 1156,2334.32 1156,2192.95 1209,2139.95 1209,2026.76 v1(1181.57,1999.33) 1209,1971.9 1209,1860.05 1158.95,1810 967,1810 935.5,1841.5 v1(935.5,1872.17) 935.5,1946.22 ; Z9.1@1144.68,2535 v1(1144.68,2569.68) ; v1(1239.68,2370) 1207.34,2337.66 1207.34,2212.34 1260,2159.68 1260,2084.45 ; Z13.1@1239.68,2400 1239.68,2617.68 1276,2654 1276,2698 ; C191.2@1280,2484.68 v1(1280,2515) ; v1(1319.37,2370.32) 1319.68,2370.63 C55.2@1319.68,2400 ; C68.2@1535.2,500.32 v1(1565,500.32) ; U13.15@1535.2,829.8 v1(1535.2,919.8) 1535.2,935.68 1559.2,959.68 C69.2@1585,959.68 ; v1(1702,2925) C187.2@1735.32,2925 ; U15.5@1956.22,809.5 v1(1956.22,870) ; v1(2022.12,500.32) R77.2@2056.22,500.32 ; R78.2@2056.22,959.68 v1(2056.22,986.48) ; C76.2@2106.22,959.68 v1(2106.22,986.48) ; v1(2128,1286.1) 2128,1241.68 2140,1229.68 C94.2@2185,1229.68 ; C91.2@2245.32,1260 2217,1288.32 v1(2217,1313.94) 2185,1345.94 2185,1491.19 v1(2217,1523.19) 2271,1577.19 v1(2276.36,1577.19) 2279.68,1580.51 C86.2@2279.68,1645 ; v1(2385,1158.52) R98.2@2385,1185.32 C92.2@2345,1185.32 2345,1006 2357,994 v1(2409.72,994) ; Y1.4@2409.72,1055.47 v1(2409.72,994) ; v1(2425,1158.52) C83.2@2425,1185.32 ; C84.2@2490,1185.32 v1(2490,1158.52) 2500.28,1148.24 Y1.2@2500.28,1114.53 2532,1114.53 2544,1102.53 2544,1006 2532,994 v1(2409.72,994) ; U14.5@2511.22,809.5 v1(2511.22,870) ; v1(2570,1158.52) R116.2@2570,1185.32 ; v1(2575,500.32) R75.2@2611.22,500.32 ; R76.2@2611.22,959.68 v1(2611.22,990) ; v1(2653.36,2360) 2658.36,2355 R155.2@2685.32,2355 ; C75.2@2661.22,959.68 v1(2661.22,990) ; v1(2675,1060) C102.2@2675,1090.32 ; v1(2715,1060) C98.2@2715,1090.32 ; C162.2@2740,959.68 v1(2740,990) ; C87.2@2755,1129.68 v1(2755,1158.52) C82.2@2755,1185.32 ; v1(2795,1158.52) C81.2@2795,1185.32 ; R105.2@2829.68,1430 v1(2860,1430) ; R103.2@2829.68,1550 v1(2860,1550) C104.2@2890.32,1550 ; R104.2@2829.68,1590 v1(2860,1590) C103.2@2890.32,1590 ; C79.2@2929.68,1305 C80.2@2929.68,1345 v1(2960,1345) ; C90.2@2930,1129.68 v1(2930,1160) ; C105.2@3050,1470.32 v1(3080.32,1470.32) ; 3095.75,2094.25 3105.02,2103.52 v1(3375,2103.52) ; 3143.3,2019.3 3146.59,2022.59 3238.41,2022.59 v1(3269,1992) 3367.65,1893.35 3367.65,1761.17 v1(3409.41,1719.41) 3570.59,1719.41 3600,1690 v1(3600,1550) v1(3600,1465) 3600,933 3635,898 3698,898 3710,910 3710,969.37 v1(3680,999.37) 3680,1130.01 3660,1150.01 v1(3660,1310) v1(3660,1550) 3660,1726 v1(3607,1779) 3551,1779 3525,1805 ; C85.2@3404.68,2527.52 3404.68,2537.56 v1(3422.12,2555) 3441.47,2574.35 v1(3525.65,2574.35) 3610.75,2574.35 3686.28,2649.88 J15.16@3686.28,2664.13 ; v1(3610,2980) U18.3@3610,3009.25 U18.8@3610,3040.75 ; v1(3750,2980) U19.3@3750,3009.25 U19.8@3750,3040.75 ; v1(3927.52,1554.68) R205.2@3957.6,1554.68 ; C123.2@4005,3129.68 v1(4005,3165) ; v1(4045,3165) C122.2@4045,3129.68 4046.22,3129.68 4080.9,3095 U24.2@4125.79,3095 v1(4170,3095) ; v1(4209.37,3095) 4254.1,3095 4293.78,3055.32 C121.2@4295,3055.32 v1(4295,3020) ; D54.1@4335,319.68 v1(4335,350) ; D53.1@4415,319.68 v1(4415,350) ; v1(4420.27,725) C54.2@4465.32,725 ; v1(4435,2920) U20.3@4435,2954.25 U20.8@4435,2985.75 v1(4435,3020) ; C176.2@4525,1074.68 4525,1094.77 v1(4532.26,1102.03) ; v1(4535,725) C73.2@4565.32,725 ; C178.2@4604.68,950 4635,919.68 v1(4635,905) D18.1@4665.32,905 ; C177.2@4605,1074.68 4605,1096.03 v1(4611,1102.03) ; v1(4635,580) D12.1@4665.32,580 ; v1(4635,625) D13.1@4665.32,625 ; v1(4635,670) D14.1@4665.32,670 ; v1(4635,725) C74.2@4665.32,725 ; v1(4635,770) D15.1@4665.32,770 ; v1(4635,815) D16.1@4665.32,815 ; v1(4635,860) D17.1@4665.32,860 ; v1(4660.27,934) 4666.83,934 4679.96,947.13 U38.2@4679.96,959.48 ; v1(4735,770) 4742.95,777.95 J9.6@4822.41,777.95 ; v1(4757.19,1471.97) 4757.19,1511.91 4781.19,1535.91 U37.8@4879.51,1535.91 ; U37.5@4821.25,1220.16 4919.85,1220.16 4939.01,1201 v1(4939.01,1150) ; v1(4850,1980.63) 4791.38,1980.63 4760.31,2011.7 4760.31,2074.96 4796.08,2110.73 4796.08,2369.92 4735,2431 4735,2554 4692.97,2596.03 J17.6@4692.97,2657.04 4800.93,2765 v1(4840,2765) 4862.68,2742.32 J20.21@5135.46,2742.32 5179.75,2742.32 v1(5181,2741.07) ; v1(4910,205) C64.2@4940.32,205 ; 5073.46,2121.69 J21.23@5135.46,2121.69 ; 5085.81,2141.38 J21.24@5135.46,2141.38 ; J21.4@5135.46,1747.68 v1(5182.32,1747.68) ; J20.4@5135.46,2407.68 v1(5180,2407.68) ; J20.18@5135.46,2683.27 5185.74,2683.27 v1(5187,2682.01) ; 5196.39,2868.31 J20.25@5241.84,2868.31 5241.84,2830.24 ; 935.5,1946.22 877.72,2004 834.7,2004 v1(800,2038.7) 778,2016.7 778,1942.59 v1(800,1920.59) 860.41,1920.59 880,1901 880,1824.32 944.32,1760 1147.27,1760 v1(1152.04,1755.23) 1174.92,1755.23 1229.69,1810 1248,1810 ; 1055.29,1548.23 1114.71,1548.23 ; 1055.29,1548.23 959.88,1548.23 925.65,1514 881.12,1514 v1(846.76,1479.64) 823,1503.4 823,1573.99 v1(846.76,1597.75) 854.51,1590 1061.48,1590 ; 1055.29,1548.23 v1(1085,1518.52) 1114.71,1548.23 ; 1061.48,1590 1108.52,1590 ; 1061.48,1590 v1(1085,1613.52) 1108.52,1590 ; 1108.52,1590 1217,1590 1260,1633 1260,1798 1248,1810 ; 1114.71,1548.23 1234.32,1548.23 1301.77,1615.68 1301.77,1727.8 ; 1248,1810 1260,1822 1260,2084.45 ; 1260,2084.45 1322,2146.45 1493.68,2146.45 1522.68,2175.45 1522.68,2249.12 1525,2251.44 1525,2252 1537,2264 1601.57,2264 1624.68,2240.89 v1(1624.68,2240) 1588,2203.32 1588,2177 1515.68,2104.68 1464.09,2104.68 ; 1301.77,1727.8 1301.77,1782.66 ; 1301.77,1727.8 v1(1329.2,1755.23) 1301.77,1782.66 ; 1301.77,1782.66 1301.77,2067.13 1339.32,2104.68 1410.87,2104.68 ; 1410.87,2104.68 v1(1437.48,2078.07) 1464.09,2104.68 ; 1410.87,2104.68 1464.09,2104.68 ; v1(3375,2103.52) 3391.48,2120 3445,2120 3505.55,2180.55 3634.44,2180.55 3669.35,2145.64 v1(3669.35,2108.92) 3640.43,2080 3575,2080 3520,2025 ; v1(3375,2103.52) 3374,2102.52 3374,2049.45 3398.45,2025 ; 3398.45,2025 3520,2025 ; 3398.45,2025 3390.63,2017.18 v1(3390.63,1948) 3416.63,1922 3416.63,1800.37 v1(3438,1779) 3464,1805 3525,1805 ; 3520,2025 3550,1995 3550,1830 3525,1805
  BOTTOM w15: v1(31,2687.88) 38.81,2680.07 U12.4@126.42,2680.07 ; D2.2@853.07,2470 890.99,2507.92 J2.2@890.99,2639.93 ; v1(3866.2,2431.76) 3869.68,2435.24 C182.2@3869.68,2495 3869.68,2545.61 v1(3874.07,2550) ; v1(4805,125) C65.2@4835.32,125 ; v1(4805,165) C66.2@4835.32,165
  BOTTOM w20: v1@31,285 v1(31,287.88) v1(31,437.88) v1(31,587.88) v1(31,737.88) v1(31,887.88) v1(31,1037.88) v1(31,1187.88) v1(31,1337.88) v1(31,1487.88) v1(31,1527.25) v1(31,1566.62) v1(31,1605.99) v1(31,1637.88) v1(31,1677.25) v1(31,1716.62) v1(31,1755.99) v1(31,1787.88) v1(31,1827.25) v1(31,1859.14) v1(31,1898.51) v1(31,1937.88) v1(31,2237.88) v1(31,2387.88) v1(31,2537.88) ; 70.06,1011.58 J3.6@98.74,1011.58 ; 70.06,1169.06 J3.4@98.74,1169.06 ; 70.06,1326.54 J3.2@98.74,1326.54 ; 98.74,982.9 J3.6@98.74,1011.58 ; 98.74,1040.26 J3.6@98.74,1011.58 ; 98.74,1140.38 J3.4@98.74,1169.06 ; 98.74,1197.74 J3.4@98.74,1169.06 ; 98.74,1297.86 J3.2@98.74,1326.54 ; 98.74,1355.22 J3.2@98.74,1326.54 ; 127.42,1011.58 J3.6@98.74,1011.58 ; 127.42,1169.06 J3.4@98.74,1169.06 ; 127.42,1326.54 J3.2@98.74,1326.54 ; v1@285,31 v1(286.25,31) v1(436.25,31) v1(586.25,31) v1(736.25,31) v1(886.25,31) v1(1036.25,31) v1(1186.25,31) v1(1336.25,31) v1(1486.25,31) v1(1636.25,31) v1(1786.25,31) v1(1936.25,31) v1(2086.25,31) v1(2236.25,31) v1(2386.25,31) v1(2536.25,31) v1(2686.25,31) v1(2836.25,31) v1(2986.25,31) v1(3136.25,31) v1(3286.25,31) v1(3436.25,31) v1(3586.25,31) v1(3736.25,31) v1(3886.25,31) v1(4036.25,31) v1(4186.25,31) v1(4336.25,31) v1(4486.25,31) v1(4636.25,31) v1(4786.25,31) 5108.7,31 ; 349.28,3146.28 J1.1@376,3146.28 ; 376,3092.01 J1.1@376,3146.28 ; 402.72,3146.28 J1.1@376,3146.28 ; 491.03,2860.78 J1.2@519.7,2860.78 ; 519.7,2802.56 J1.2@519.7,2860.78 ; 519.7,2919 J1.2@519.7,2860.78 ; 548.37,2860.78 J1.2@519.7,2860.78 ; 699.63,2860.78 J1.3@728.3,2860.78 ; 728.3,2802.56 J1.3@728.3,2860.78 ; 728.3,2919 J1.3@728.3,2860.78 ; 735.08,3146.28 J1.5@761.8,3146.28 ; 756.97,2860.78 J1.3@728.3,2860.78 ; 761.8,3092.01 J1.5@761.8,3146.28 ; 788.52,3146.28 J1.5@761.8,3146.28 ; 1030,876 J5.1@1030,925 ; v1(1373.69,3197.34) v1(1523.69,3197.34) v1(1673.69,3197.34) v1(1823.69,3197.34) v1(1973.69,3197.34) v1(2123.69,3197.34) v1(2273.69,3197.34) v1(2423.69,3197.34) v1(2573.69,3197.34) v1(2613.06,3197.34) v1(2652.43,3197.34) 2945.66,3197.34 2965,3178 R114.2@2965,3134.68 ; 2727.74,105.01 J23.6@2756.42,105.01 ; 2756.42,76.33 J23.6@2756.42,105.01 ; 2756.42,133.69 J23.6@2756.42,105.01 ; 2785.1,105.01 J23.6@2756.42,105.01 ; R111.2@3005,3134.68 3005,3184 3018.34,3197.34 v1(3323.69,3197.34) v1(3473.69,3197.34) v1(3623.69,3197.34) v1(3773.69,3197.34) v1(3923.69,3197.34) v1(4073.69,3197.34) ; 3200.18,105.01 J32.4@3228.86,105.01 ; 3228.86,76.33 J32.4@3228.86,105.01 ; 3228.86,133.69 J32.4@3228.86,105.01 ; 3257.54,105.01 J32.4@3228.86,105.01 ; 3672.62,105.01 J34.4@3701.3,105.01 ; 3701.3,76.33 J34.4@3701.3,105.01 ; 3701.3,133.69 J34.4@3701.3,105.01 ; 3729.98,105.01 J34.4@3701.3,105.01 ; 4145.06,105.01 J35.4@4173.74,105.01 ; 4173.74,76.33 J35.4@4173.74,105.01 ; 4173.74,133.69 J35.4@4173.74,105.01 ; R148.2@4194.68,3180 4212.02,3197.34 v1(4223.69,3197.34) v1(4373.69,3197.34) v1(4523.69,3197.34) ; 4202.42,105.01 J35.4@4173.74,105.01 ; 4550,3179 v1(4550,3135) C113.2@4550,3094.68 C112.2@4590,3094.68 ; 4590,3179 v1(4590,3135) C112.2@4590,3094.68 ; 4630,3179 v1(4630,3135) C117.2@4630,3094.68 ; U21.2@4740.79,3095 v1(4700,3095) 4670.32,3095 C116.2@4670,3094.68 C117.2@4630,3094.68 ; v1(4823.69,3197.34) 5107.51,3197.34 ; 5165.53,344.88 J9.12@5220.05,344.88 ; 5220.05,307.86 J9.12@5220.05,344.88 ; J21.25@5241.84,2208.31 5341.69,2208.31 ; J20.26@5241.84,2281.69 5332.31,2281.69 ; 5241.84,2906.83 J20.25@5241.84,2868.31 5288.23,2868.31 ; 5274.57,344.88 J9.12@5220.05,344.88 ; 5362.69,284.99 v1(5362.69,412.23) v1(5362.69,562.23) v1(5362.69,712.23) v1(5362.69,862.23) ; v1(5362.69,1162.23) v1(5362.69,1312.23) v1(5362.69,1462.23) 5362.69,1525.17 U37.10@5351.95,1535.91 U37.10@5362.69,1546.65 ; v1(5362.69,1912.23) v1(5362.69,2062.23) ; v1(5362.69,2401.6) v1(5362.69,2512.23) v1(5362.69,2662.23) v1(5362.69,2812.23) 5362.69,2942.16 ; C112.2@4590,3094.68 C117.2@4630,3094.68
  BOTTOM w30: v1(3510.63,3125.63) v1(3510.63,3165) ; J9.13@4842.1,380.32 4900,438.22 v1(4900,461.16) ; J9.11@5220.05,955.12 5329.12,955.12 ; J21.26@5241.84,1621.69 5329.72,1621.69
  other v1: 3865,140 4355,140 2545,165 330,205 480,205 630,205 780,205 930,205 1080,205 1230,205 1380,205 1530,205 1980,205 2130,205 2280,205 2430,205 3390,205 3700,205 1748.02,223.02 1623.85,225 1380,355 1530,355 4105.31,358.91 4144.68,358.91 750,410 900,410 1530,430 1216.89,430.63 1256.26,430.63 1295.63,430.63 1335,430.63 1374.37,430.63 1413.74,430.63 4065.94,473.43 4184.06,473.43 4184.06,512.8 2769.1,539.68 2808.47,539.68 4065.94,552.17 4184.06,552.17 900,560 2769.1,579.05 2808.47,579.05 4065.94,591.54 4184.06,591.54 2769.1,618.42 2808.47,618.42 4184.06,630.91 4057.43,670.28 4097.43,670.28 4147.57,670.28 4184.06,670.28 4057.43,709.65 4097.43,709.65 4147.57,709.65 4184.06,709.65 780.63,725 2856.77,770.03 2896.14,770.03 4057.43,788.39 4097.43,788.39 4147.57,788.39 4184.06,788.39 4223.43,788.39 4262.8,788.39 4302.17,788.39 4420.27,798.39 5029.26,804.22 4420.27,837.76 5029.26,843.59 1720,870 1759.37,870 1798.74,870 1838.11,870 1877.48,870 2244.08,872.19 2284.08,872.19 2324.08,872.19 2364.08,872.19 2404.08,872.19 381.69,874.05 421.06,874.05 460.43,874.05 776.69,874.05 816.06,874.05 1106.06,874.05 1145.43,874.05 4065.94,877.13 4105.31,877.13 4144.68,877.13 4184.05,877.13 4223.42,877.13 4262.79,877.13 4302.16,877.13 4341.53,877.13 4380.9,877.13 4420.27,877.13 4939.01,932.95 4939.01,972.32 4978,972.32 336.8,980 420,980 3719.37,999.37 3758.74,999.37 4939.01,1011.69 4978.38,1011.69 224.21,1024.05 4939.01,1051.06 4978.38,1051.06 224.21,1063.42 263.58,1063.42 302.95,1063.42 342.32,1063.42 381.69,1063.42 421.06,1063.42 5075.37,1154.68 224.21,1174.05 5075.37,1194.05 224.21,1213.42 263.58,1213.42 302.95,1213.42 342.32,1213.42 381.69,1213.42 421.06,1213.42 3995,1269.63 4034.37,1269.63 4073.74,1269.63 5075.37,1284.68 3995,1309 4034.37,1309 4073.74,1309 184.84,1324.05 5036,1324.05 5075.37,1324.05 224.21,1363.42 340,1365 380,1365 5075.37,1366.32 2435.63,1395.63 2475,1395.63 4556.37,1402 4595.74,1402 4635.11,1402 2435.63,1435 2475,1435 2514.37,1435 4556.37,1441.37 4595.74,1441.37 4635.11,1441.37 5075.05,1445 3800,1463 3839.37,1463 3878.74,1463 2435.63,1474.37 2475,1474.37 2514.37,1474.37 335,1490 375,1490 640.23,1548.15 640.23,1587.52 249.37,1605.11 640.23,1626.89 249.37,1644.48 5339.8,1668.94 249.37,1683.85 4444,1693 4635,1695 600.86,1705.63 640.23,1705.63 5339.8,1708.31 249.37,1723.22 334.92,1722.52 600.86,1745 640.23,1745 4524,1748.31 5339.8,1747.68 335,1761.89 210,1762.59 249.37,1762.59 4444,1813 4523,1814 315,1835.63 4524,1874 605,1924.37 4524,1929 605,1963.74 165,1974.77 204.37,1974.77 605,2003.11 204.37,2014.14 4850,2020 4935,2020 605,2042.48 5036.42,2042.95 5075.79,2042.95 476.07,2047.51 4850,2059.37 5036.42,2082.32 5075.79,2082.32 436.7,2086.88 476.07,2086.88 512.28,2086.88 4850,2110.63 436.7,2126.25 476.07,2126.25 512.28,2126.25 165,2156.63 205,2156.63 5036.42,2161.06 5075.79,2161.06 476.07,2165.62 512.28,2165.62 4850,2189.37 5036.42,2200.43 5075.79,2200.43 590,2204.25 4941.2,2235 2605.59,2240.63 2605.59,2280 4850,2300.63 5036.42,2305 5075.79,2305 864.79,2355 215,2370 255,2370 295,2370 335,2370 4850,2379.37 215,2415 864.79,2427.44 825.42,2427.99 3787.46,2431.76 615.63,2479.26 205,2500 245,2500 615.63,2518.63 694.37,2518.63 5293,2534.81 205,2545 615.63,2558 694.37,2558 5293,2650.06 168.62,2735 119.68,2737 871.26,2807.26 871.26,2846.63 910.63,2886 950,2886 1202,2886 1241.37,2886 1280.74,2886 4883.51,2888.51 4915,2888.51 4946.49,2888.51 168.62,2900 4883.51,2920 4915,2920 4946.49,2920 910.63,2925.37 1241.37,2925.37 1280.74,2925.37 1490.37,2942 4883.51,2951.49 4915,2951.49 4946.49,2951.49 1037.22,3050.07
